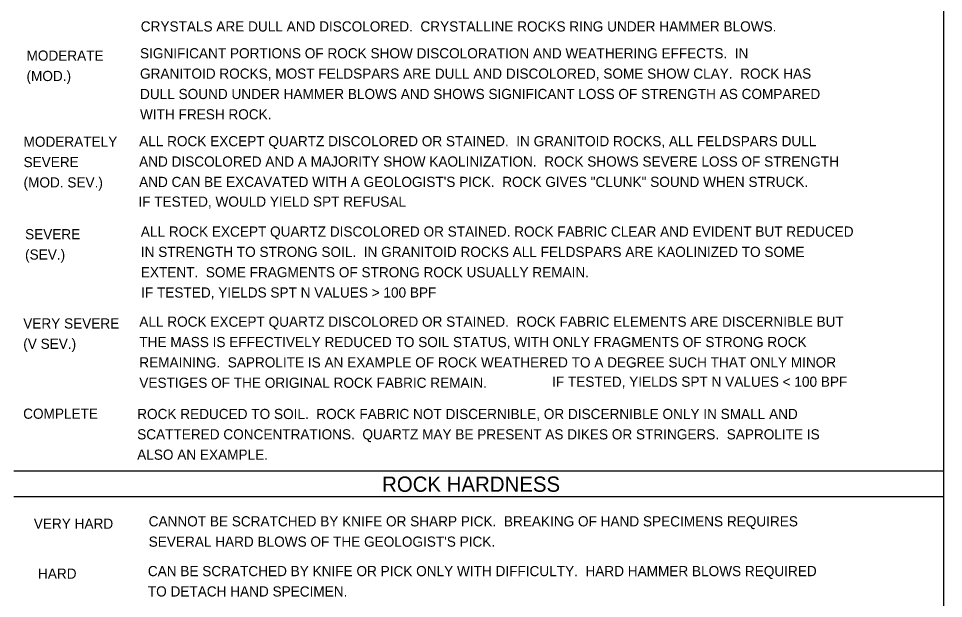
# Model space of a CAD drawing. Extents: x 278710 to 279187, y 171464 to 171625.
# Drawn here: x 279081.88 to 279121.33, y 171516.98 to 171541.71 of the extents above; entities that cross this region are included whole.
import ezdxf

# ---------------------------------------------------------------- set-up
doc = ezdxf.new("R2010")
doc.units = 0
doc.layers.add('Geotech Sheets and Borders Cell', color=7, linetype='Continuous')

msp = doc.modelspace()

# ---------------------------------------------------------------- linework, layer by layer
at = {"layer": 'Geotech Sheets and Borders Cell'}
for p, q in [((279121.332, 171566.02), (279121.332, 171485.806)), ((279081.678, 171522.419), (279121.332, 171522.419)), ((279081.678, 171521.334), (279121.332, 171521.334))]:
    msp.add_line(p, q, dxfattribs=at)

# ---------------------------------------------------------------- texts
for s, height, p in [('CRYSTALS ARE DULL AND DISCOLORED.  CRYSTALLINE ROCKS RING UNDER HAMMER BLOWS.', 0.43381, (279087.097, 171541.155)), ('SIGNIFICANT PORTIONS OF ROCK SHOW DISCOLORATION AND WEATHERING EFFECTS.  IN ', 0.43381, (279087.066, 171540.01)), ('MODERATE', 0.4338, (279082.225, 171539.91)), ('GRANITOID ROCKS, MOST FELDSPARS ARE DULL AND DISCOLORED, SOME SHOW CLAY.  ROCK HAS ', 0.43381, (279087.066, 171539.142)), ('(MOD.)', 0.4338, (279082.225, 171539.042)), ('DULL SOUND UNDER HAMMER BLOWS AND SHOWS SIGNIFICANT LOSS OF STRENGTH AS COMPARED ', 0.43381, (279087.066, 171538.274)), ('WITH FRESH ROCK.', 0.43381, (279087.066, 171537.407)), ('MODERATELY', 0.4338, (279082.099, 171536.24)), ('ALL ROCK EXCEPT QUARTZ DISCOLORED OR STAINED.  IN GRANITOID ROCKS, ALL FELDSPARS DULL ', 0.43381, (279087.027, 171536.262)), ('SEVERE', 0.4338, (279082.099, 171535.372)), ('AND DISCOLORED AND A MAJORITY SHOW KAOLINIZATION.  ROCK SHOWS SEVERE LOSS OF STRENGTH ', 0.43381, (279087.027, 171535.394)), ('(MOD. SEV.)', 0.43381, (279082.099, 171534.505)), ('AND CAN BE EXCAVATED WITH A GEOLOGIST\'S PICK.  ROCK GIVES "CLUNK" SOUND WHEN STRUCK.', 0.43381, (279087.027, 171534.526)), ('IF TESTED, WOULD YIELD SPT REFUSAL', 0.43381, (279086.997, 171533.685)), ('SEVERE', 0.4338, (279082.164, 171532.297)), ('ALL ROCK EXCEPT QUARTZ DISCOLORED OR STAINED. ROCK FABRIC CLEAR AND EVIDENT BUT REDUCED ', 0.43381, (279087.101, 171532.409)), ('(SEV.)', 0.4338, (279082.164, 171531.429)), ('IN STRENGTH TO STRONG SOIL.  IN GRANITOID ROCKS ALL FELDSPARS ARE KAOLINIZED TO SOME ', 0.43381, (279087.101, 171531.542)), ('EXTENT.  SOME FRAGMENTS OF STRONG ROCK USUALLY REMAIN.', 0.43381, (279087.101, 171530.675)), ('IF TESTED, YIELDS SPT N VALUES > 100 BPF', 0.43381, (279087.114, 171529.811)), ('VERY SEVERE', 0.43381, (279082.086, 171528.492)), ('ALL ROCK EXCEPT QUARTZ DISCOLORED OR STAINED.  ROCK FABRIC ELEMENTS ARE DISCERNIBLE BUT ', 0.43381, (279087.036, 171528.566)), ('THE MASS IS EFFECTIVELY REDUCED TO SOIL STATUS, WITH ONLY FRAGMENTS OF STRONG ROCK ', 0.43381, (279087.036, 171527.698)), ('(V SEV.)', 0.4338, (279082.086, 171527.625)), ('REMAINING.  SAPROLITE IS AN EXAMPLE OF ROCK WEATHERED TO A DEGREE SUCH THAT ONLY MINOR ', 0.43381, (279087.036, 171526.831)), ('VESTIGES OF THE ORIGINAL ROCK FABRIC REMAIN.', 0.43381, (279087.036, 171525.963)), ('IF TESTED, YIELDS SPT N VALUES < 100 BPF', 0.43381, (279104.64, 171526.007)), ('COMPLETE', 0.4338, (279082.082, 171524.644)), ('ROCK REDUCED TO SOIL.  ROCK FABRIC NOT DISCERNIBLE, OR DISCERNIBLE ONLY IN SMALL AND ', 0.43381, (279086.945, 171524.631)), ('SCATTERED CONCENTRATIONS.  QUARTZ MAY BE PRESENT AS DIKES OR STRINGERS.  SAPROLITE IS ', 0.43381, (279086.945, 171523.764)), ('ALSO AN EXAMPLE.', 0.43381, (279086.945, 171522.896)), ('ROCK HARDNESS', 0.6507, (279097.391, 171521.53)), ('VERY HARD', 0.4338, (279082.537, 171519.955)), ('CANNOT BE SCRATCHED BY KNIFE OR SHARP PICK.  BREAKING OF HAND SPECIMENS REQUIRES ', 0.43381, (279087.435, 171520.055)), ("SEVERAL HARD BLOWS OF THE GEOLOGIST'S PICK.", 0.43381, (279087.435, 171519.188)), ('CAN BE SCRATCHED BY KNIFE OR PICK ONLY WITH DIFFICULTY.  HARD HAMMER BLOWS REQUIRED ', 0.43381, (279087.4, 171517.933)), ('HARD', 0.4338, (279082.715, 171517.825)), ('TO DETACH HAND SPECIMEN.', 0.43381, (279087.4, 171517.066))]:
    msp.add_text(s, height=height, dxfattribs=at).set_placement(p)

doc.saveas('drawing.dxf')
